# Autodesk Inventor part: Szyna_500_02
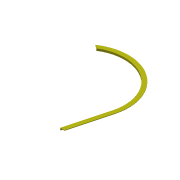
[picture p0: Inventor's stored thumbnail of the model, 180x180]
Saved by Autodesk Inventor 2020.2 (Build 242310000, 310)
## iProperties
Created: 2014-10
Part Number: Szyna_500_02
Material: Ogólny
Document SubType Name: Modeling
Designer: F.Stasiak
Density: 1 g/cm^3
Appearance: Żółta
Catalog Web Link: www.expertbooks.pl
Manager: www.cadconsulting.pl
Company: Fabian Stasiak CAD Consulting
Author: F.Stasiak
Subject: Zbiór ćwiczeń. Autodesk Inventor 2020. Kurs Professional
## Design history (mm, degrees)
derived "Szyna_500_01.ipt"
  sketch "Szkic1"
    geometry: L1 (0, 0)-(-258.819, 965.926) reference; L2 (103.528, 0)-(-162.226, 991.808) reference; L3 (0, 0)-(103.528, 0) reference; L4 (1331.492, 2100)-(1419.027, 2162.423) reference; A1 r 1000 centre (803.699, 1250.627) between (1331.492, 2100) and (-162.226, 991.808) reference; A2 r 1100 centre (803.699, 1250.627) between (1419.027, 2162.423) and (-258.819, 965.926) reference
    dimensions: "d0" = 10 dimension on L1.start L1.end L1 L2.start L2.end L2 L4.start L3 A1.centre A1 A2.centre A2 L4.end L4
feature "Bryła1::Szyna_500_01.ipt" dims "d0" = 10
tag "Bryła wyprowadzona1"
node "Bryła1"
